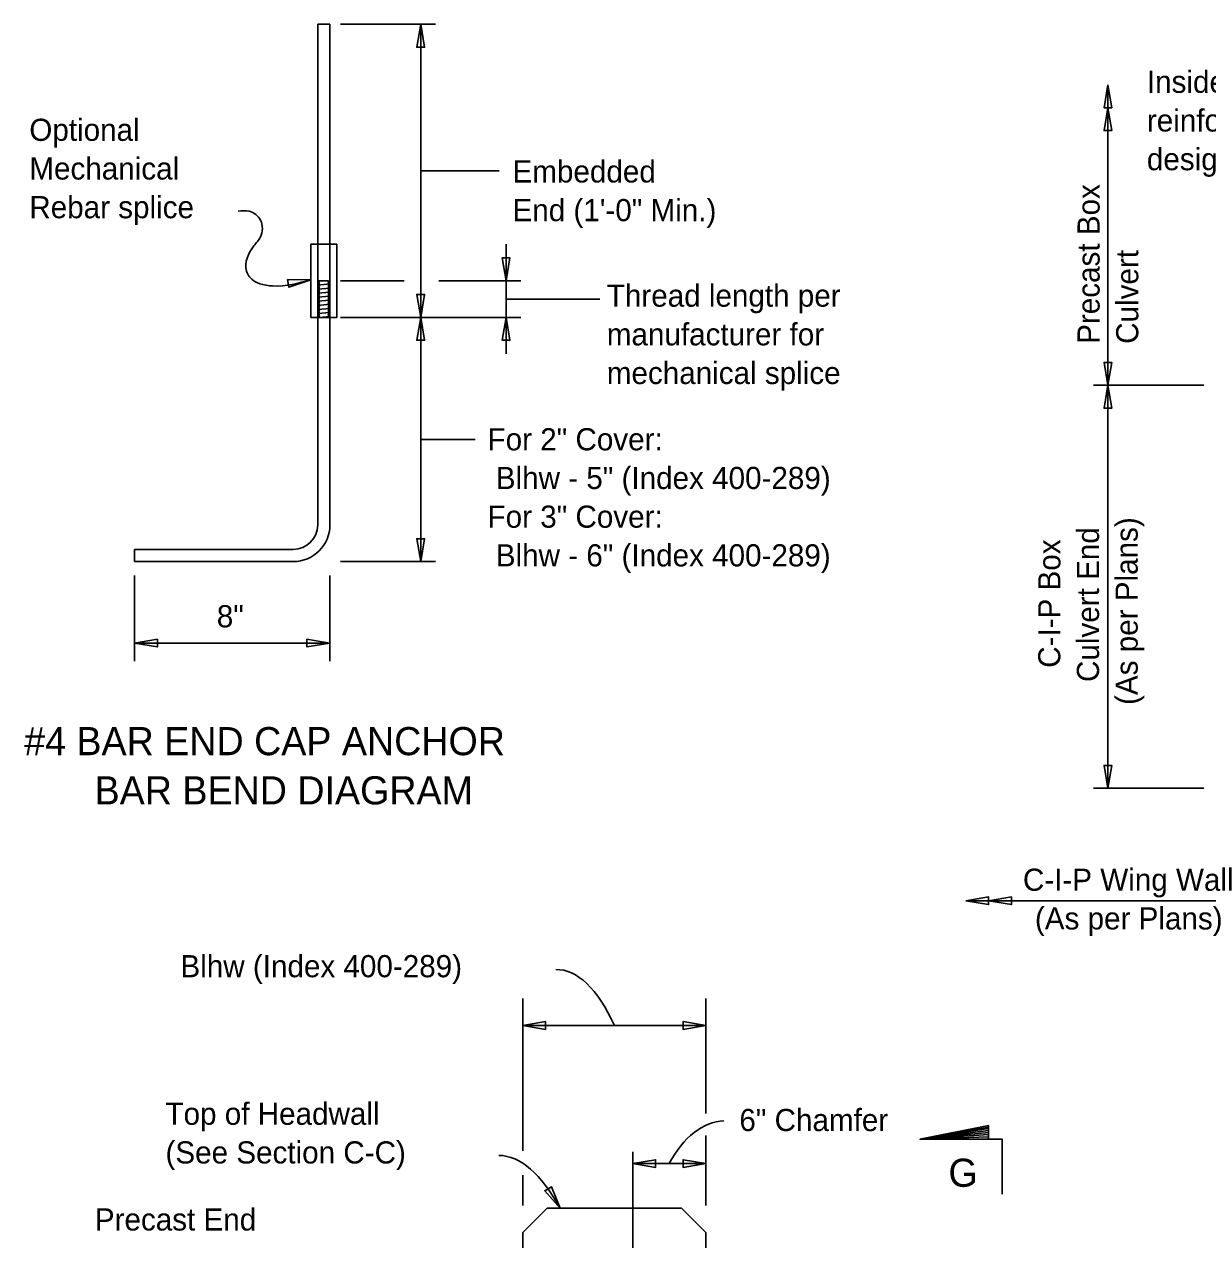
# Model space of a CAD drawing. Extents: x 10605.2 to 10672.7, y 76423.8 to 76450.2.
# Drawn here: x 10619.57 to 10627.65, y 76438.73 to 76447.02 of the extents above; entities that cross this region are included whole.
import ezdxf

# ---------------------------------------------------------------- set-up
doc = ezdxf.new("R2010")
doc.units = 0
for name, color, linetype in [('AdhocPoint_dp', 7, 'Continuous'), ('Leader', 7, 'Continuous'), ('Patterning', 7, 'Continuous'), ('PlotBorder_dp', 7, 'Continuous'), ('SheetBorder_dp', 7, 'Continuous')]:
    doc.layers.add(name, color=color, linetype=linetype)

msp = doc.modelspace()

# ---------------------------------------------------------------- linework, layer by layer
at = {"layer": 'AdhocPoint_dp'}
for p, q in [((10621.7326, 76447.0217), (10622.3813, 76447.0217)), ((10622.2798, 76447.0217), (10622.2798, 76445.0217)), ((10626.9707, 76446.6083), (10626.9707, 76444.558)), ((10622.2798, 76446.0217), (10622.8162, 76446.0217)), ((10622.8626, 76445.5217), (10622.8626, 76445.2717)), ((10621.7326, 76445.2717), (10622.1672, 76445.2717)), ((10622.4027, 76445.2717), (10622.9625, 76445.2717)), ((10622.8626, 76445.2717), (10622.8626, 76445.0217)), ((10622.8626, 76445.1467), (10623.5022, 76445.1467)), ((10621.7326, 76445.0217), (10622.9625, 76445.0217)), ((10622.2798, 76445.0217), (10622.2798, 76443.355)), ((10622.8626, 76445.0217), (10622.8626, 76444.7717)), ((10627.6247, 76444.558), (10626.8725, 76444.558)), ((10626.9707, 76444.558), (10626.9707, 76441.808)), ((10622.2798, 76444.1884), (10622.6515, 76444.1884)), ((10621.7326, 76443.355), (10622.3813, 76443.355)), ((10620.3267, 76443.2591), (10620.3267, 76442.6761)), ((10621.6601, 76443.2591), (10621.6601, 76442.6761)), ((10620.3267, 76442.7986), (10621.6601, 76442.7986)), ((10627.6247, 76441.808), (10626.8725, 76441.808)), ((10628.4224, 76441.0403), (10625.9996, 76441.0403)), ((10622.9768, 76439.3334), (10622.9768, 76440.3737)), ((10624.2268, 76439.5874), (10624.2268, 76440.3737)), ((10624.2268, 76440.1889), (10622.9768, 76440.1889)), ((10624.2268, 76438.9598), (10624.2268, 76439.4386)), ((10625.687, 76439.4124), (10626.1558, 76439.4949)), ((10626.1558, 76439.4849), (10625.687, 76439.4124)), ((10625.687, 76439.4124), (10626.1558, 76439.4724)), ((10626.1558, 76439.4587), (10625.687, 76439.4124)), ((10625.687, 76439.4124), (10626.1558, 76439.4449)), ((10626.1558, 76439.4299), (10625.687, 76439.4124)), ((10623.7268, 76437.7939), (10623.7268, 76439.3272)), ((10624.2268, 76439.2464), (10623.7268, 76439.2464)), ((10622.9768, 76438.9598), (10622.9768, 76439.168))]:
    msp.add_line(p, q, dxfattribs=at)
for points in [[(10622.2798, 76447.0217), (10622.2533, 76446.8656), (10622.3062, 76446.8656)], [(10626.9707, 76446.6083), (10626.9442, 76446.4522), (10626.9971, 76446.4522)], [(10626.9707, 76446.4522), (10626.9442, 76446.296), (10626.9971, 76446.296)], [(10622.8626, 76445.2717), (10622.889, 76445.4279), (10622.8361, 76445.4279)], [(10621.5301, 76445.2785), (10621.3717, 76445.2796), (10621.3802, 76445.2274)], [(10622.2798, 76445.0217), (10622.3062, 76445.1779), (10622.2533, 76445.1779)], [(10622.2798, 76445.0217), (10622.2533, 76444.8656), (10622.3062, 76444.8656)], [(10622.8626, 76445.0217), (10622.8361, 76444.8656), (10622.889, 76444.8656)], [(10626.9707, 76444.558), (10626.9971, 76444.7141), (10626.9442, 76444.7141)], [(10626.9707, 76444.558), (10626.9442, 76444.4018), (10626.9971, 76444.4018)], [(10622.2798, 76443.355), (10622.3062, 76443.5112), (10622.2533, 76443.5112)], [(10620.3267, 76442.7986), (10620.4829, 76442.7721), (10620.4829, 76442.825)], [(10621.6601, 76442.7986), (10621.5039, 76442.825), (10621.5039, 76442.7721)], [(10626.9707, 76441.808), (10626.9971, 76441.9641), (10626.9442, 76441.9641)], [(10625.9996, 76441.0403), (10626.1558, 76441.0138), (10626.1558, 76441.0668)], [(10626.1558, 76441.0403), (10626.312, 76441.0138), (10626.312, 76441.0668)], [(10622.9767, 76440.1889), (10623.1329, 76440.1624), (10623.1329, 76440.2154)], [(10624.2268, 76440.1889), (10624.0706, 76440.2154), (10624.0706, 76440.1624)], [(10623.7268, 76439.2464), (10623.883, 76439.2199), (10623.883, 76439.2728)], [(10624.2268, 76439.2464), (10624.0706, 76439.2728), (10624.0706, 76439.2199)], [(10623.2315, 76438.9418), (10623.1721, 76439.0887), (10623.1271, 76439.0609)]]:
    msp.add_lwpolyline(points, close=True, dxfattribs=at)
msp.add_lwpolyline([(10626.2495, 76439.0374), (10626.2495, 76439.4124), (10625.687, 76439.4124), (10626.1558, 76439.5062), (10626.1558, 76439.4124)], dxfattribs=at)
for centre, major_axis, ratio, start_param, end_param in [((10623.2476, 76439.1459), (0.045, -1.4244), 0.393454, 2.379989, 3.141593), ((10624.384, 76438.5593), (0.0345, -0.9779), 0.560741, 3.141593, 3.913766), ((10622.7291, 76435.3442), (-0.0839, -3.9584), 0.261149, 2.716835, 3.141593)]:
    msp.add_ellipse(centre, major_axis=major_axis, ratio=ratio, start_param=start_param, end_param=end_param, dxfattribs=at)
at = {"layer": 'Leader'}
msp.add_spline([(10621.0338, 76445.7462), (10621.1102, 76445.7462), (10621.1866, 76445.6851), (10621.1866, 76445.5705), (10621.1407, 76445.5094), (10621.0911, 76445.3375), (10621.1122, 76445.2972), (10621.2694, 76445.2362), (10621.5301, 76445.2785)], degree=3, dxfattribs=at)
at = {"layer": 'Patterning'}
for p, q in [((10621.5769, 76445.0217), (10621.5769, 76447.0217)), ((10621.6601, 76447.0217), (10621.5769, 76447.0217)), ((10621.6601, 76445.0217), (10621.6601, 76447.0217)), ((10621.5301, 76445.0217), (10621.5301, 76445.5217)), ((10621.7069, 76445.5217), (10621.5301, 76445.5217)), ((10621.7069, 76445.0217), (10621.7069, 76445.5217)), ((10621.5969, 76445.2717), (10621.5769, 76445.27)), ((10621.5799, 76445.2717), (10621.5769, 76445.27)), ((10621.5769, 76445.27), (10621.591, 76445.2643)), ((10621.591, 76445.2643), (10621.5769, 76445.2562)), ((10621.5769, 76445.2562), (10621.591, 76445.2504)), ((10621.591, 76445.2504), (10621.5769, 76445.2423)), ((10621.6604, 76445.2495), (10621.5769, 76445.2423)), ((10621.5769, 76445.2423), (10621.591, 76445.2366)), ((10621.591, 76445.2366), (10621.5769, 76445.2285)), ((10621.5769, 76445.2285), (10621.591, 76445.2227)), ((10621.6507, 76445.2717), (10621.5799, 76445.2717)), ((10621.6507, 76445.2717), (10621.6462, 76445.2692)), ((10621.6462, 76445.2692), (10621.6604, 76445.2634)), ((10621.6604, 76445.2634), (10621.6462, 76445.2553)), ((10621.6462, 76445.2553), (10621.6604, 76445.2495)), ((10621.6604, 76445.2495), (10621.6462, 76445.2415)), ((10621.6462, 76445.2415), (10621.6604, 76445.2357)), ((10621.6604, 76445.2357), (10621.6462, 76445.2276)), ((10621.6462, 76445.2276), (10621.6604, 76445.2218)), ((10621.591, 76445.2227), (10621.5769, 76445.2146)), ((10621.6604, 76445.2218), (10621.5769, 76445.2146)), ((10621.5769, 76445.2146), (10621.591, 76445.2089)), ((10621.591, 76445.2089), (10621.5769, 76445.2008)), ((10621.5769, 76445.2008), (10621.591, 76445.195)), ((10621.591, 76445.195), (10621.5769, 76445.1869)), ((10621.6604, 76445.1941), (10621.5769, 76445.1869)), ((10621.5769, 76445.1869), (10621.591, 76445.1812)), ((10621.591, 76445.1812), (10621.5769, 76445.173)), ((10621.5769, 76445.173), (10621.591, 76445.1673)), ((10621.591, 76445.1673), (10621.5769, 76445.1592)), ((10621.6604, 76445.1664), (10621.5769, 76445.1592)), ((10621.5769, 76445.1592), (10621.591, 76445.1535)), ((10621.591, 76445.1535), (10621.5769, 76445.1453)), ((10621.5769, 76445.1453), (10621.591, 76445.1396)), ((10621.6604, 76445.2218), (10621.6462, 76445.2138)), ((10621.6462, 76445.2138), (10621.6604, 76445.2079)), ((10621.6604, 76445.2079), (10621.6462, 76445.1999)), ((10621.6462, 76445.1999), (10621.6604, 76445.1941)), ((10621.6604, 76445.1941), (10621.6462, 76445.1861)), ((10621.6462, 76445.1861), (10621.6604, 76445.1802)), ((10621.6604, 76445.1802), (10621.6462, 76445.1722)), ((10621.6462, 76445.1722), (10621.6604, 76445.1664)), ((10621.6604, 76445.1664), (10621.6462, 76445.1584)), ((10621.6462, 76445.1584), (10621.6604, 76445.1525)), ((10621.6604, 76445.1525), (10621.6462, 76445.1445)), ((10621.6462, 76445.1445), (10621.6604, 76445.1387)), ((10621.591, 76445.1396), (10621.5769, 76445.1315)), ((10621.6604, 76445.1387), (10621.5769, 76445.1315)), ((10621.5769, 76445.1315), (10621.591, 76445.1258)), ((10621.591, 76445.1258), (10621.5769, 76445.1176)), ((10621.5769, 76445.1176), (10621.591, 76445.1119)), ((10621.591, 76445.1119), (10621.5769, 76445.1038)), ((10621.6604, 76445.111), (10621.5769, 76445.1038)), ((10621.5769, 76445.1038), (10621.591, 76445.098)), ((10621.591, 76445.098), (10621.5769, 76445.0899)), ((10621.5769, 76445.0899), (10621.591, 76445.0842)), ((10621.591, 76445.0842), (10621.5769, 76445.0761)), ((10621.6604, 76445.0833), (10621.5769, 76445.0761)), ((10621.5769, 76445.0761), (10621.591, 76445.0703)), ((10621.591, 76445.0703), (10621.5769, 76445.0622)), ((10621.5769, 76445.0622), (10621.591, 76445.0565)), ((10621.6604, 76445.1387), (10621.6462, 76445.1307)), ((10621.6462, 76445.1307), (10621.6604, 76445.1248)), ((10621.6604, 76445.1248), (10621.6462, 76445.1168)), ((10621.6462, 76445.1168), (10621.6604, 76445.111)), ((10621.6604, 76445.111), (10621.6462, 76445.1029)), ((10621.6462, 76445.1029), (10621.6604, 76445.0971)), ((10621.6604, 76445.0971), (10621.6462, 76445.0891)), ((10621.6462, 76445.0891), (10621.6604, 76445.0833)), ((10621.6604, 76445.0833), (10621.6462, 76445.0752)), ((10621.6462, 76445.0752), (10621.6604, 76445.0694)), ((10621.6604, 76445.0694), (10621.6462, 76445.0614)), ((10621.6462, 76445.0614), (10621.6604, 76445.0555)), ((10621.7069, 76445.0217), (10621.5301, 76445.0217)), ((10621.591, 76445.0565), (10621.5769, 76445.0484)), ((10621.6604, 76445.0555), (10621.5769, 76445.0484)), ((10621.5769, 76445.0484), (10621.591, 76445.0426)), ((10621.591, 76445.0426), (10621.5769, 76445.0345)), ((10621.5769, 76445.0345), (10621.591, 76445.0288)), ((10621.5769, 76443.6048), (10621.5769, 76445.0217)), ((10621.6601, 76445.0217), (10621.5769, 76445.0217)), ((10621.591, 76445.0288), (10621.5788, 76445.0217)), ((10621.6604, 76445.0278), (10621.5896, 76445.0217)), ((10621.6604, 76445.0555), (10621.6462, 76445.0475)), ((10621.6462, 76445.0475), (10621.6604, 76445.0417)), ((10621.6604, 76445.0417), (10621.6462, 76445.0337)), ((10621.6462, 76445.0337), (10621.6604, 76445.0278)), ((10621.6604, 76445.0278), (10621.6496, 76445.0217)), ((10621.6601, 76443.6048), (10621.6601, 76445.0217)), ((10620.3267, 76443.355), (10620.3267, 76443.4382)), ((10620.3267, 76443.4382), (10621.4103, 76443.4382)), ((10620.3267, 76443.355), (10621.4103, 76443.355))]:
    msp.add_line(p, q, dxfattribs=at)
for radius, start, end in [(0.1666, 270.00196, 0.00066), (0.2498, 270.00477, 0.00093)]:
    msp.add_arc((10621.4103, 76443.6048), radius, start, end, dxfattribs=at)
at = {"layer": 'PlotBorder_dp'}
for p, q in [((10623.1435, 76438.9418), (10622.9768, 76438.7751)), ((10623.1435, 76438.9418), (10624.0601, 76438.9418)), ((10624.2268, 76438.7751), (10624.0601, 76438.9418)), ((10622.9768, 76438.7751), (10622.9768, 76432.2752)), ((10624.2268, 76438.7751), (10624.2268, 76432.2752))]:
    msp.add_line(p, q, dxfattribs=at)

# ---------------------------------------------------------------- texts
at = {"layer": 'AdhocPoint_dp'}
for s, height, p in [('Inside vertical wall', 0.1512, (10627.2364, 76446.5539)), ('reinforcing (See C-I-P', 0.1512, (10627.2364, 76446.2899)), ('Optional', 0.1512, (10619.6087, 76446.2262)), ('design in plans)', 0.1512, (10627.2364, 76446.0259)), ('Mechanical', 0.1512, (10619.6087, 76445.9622)), ('Embedded', 0.1512, (10622.9066, 76445.942)), ('Rebar splice', 0.1512, (10619.6087, 76445.6982)), ('End (1\'-0" Min.)', 0.1512, (10622.9066, 76445.678)), ('Thread length per', 0.1512, (10623.5501, 76445.0945)), ('manufacturer for', 0.1512, (10623.5501, 76444.8305)), ('mechanical splice', 0.1512, (10623.5501, 76444.5665)), ('For 2" Cover:', 0.1512, (10622.7363, 76444.1141)), (' Blhw - 5" (Index 400-289)', 0.1512, (10622.7363, 76443.8501)), ('For 3" Cover:', 0.1512, (10622.7363, 76443.5861)), (' Blhw - 6" (Index 400-289)', 0.1512, (10622.7363, 76443.3221)), ('#4 BAR END CAP ANCHOR', 0.192, (10619.5734, 76442.0337)), ('BAR BEND DIAGRAM', 0.192, (10620.0543, 76441.6977)), ('C-I-P Wing Wall', 0.1512, (10626.3903, 76441.1082)), ('(As per Plans)', 0.1512, (10626.4722, 76440.8442)), ('Blhw (Index 400-289)', 0.1512, (10620.6402, 76440.5182)), ('Top of Headwall', 0.1512, (10620.5381, 76439.5112)), ('(See Section C-C)', 0.1512, (10620.5381, 76439.2472)), ('Precast End', 0.1512, (10620.0559, 76438.7896))]:
    msp.add_text(s, height=height, dxfattribs=at).set_placement(p)
for s, p in [('Precast Box', (10626.9138, 76444.8409)), ('Culvert', (10627.1778, 76444.8409)), ('Culvert End', (10626.9098, 76442.5332)), ('(As per Plans)', (10627.1738, 76442.3765)), ('C-I-P Box', (10626.6458, 76442.63))]:
    msp.add_text(s, height=0.1512, rotation=90, dxfattribs=at).set_placement(p)
at = {"layer": 'SheetBorder_dp'}
for s, height, p in [('8"', 0.1512, (10620.8883, 76442.9064)), ('6" Chamfer', 0.1512, (10624.4549, 76439.4684)), ('G', 0.192, (10625.8818, 76439.088))]:
    msp.add_text(s, height=height, dxfattribs=at).set_placement(p)

doc.saveas('drawing.dxf')
